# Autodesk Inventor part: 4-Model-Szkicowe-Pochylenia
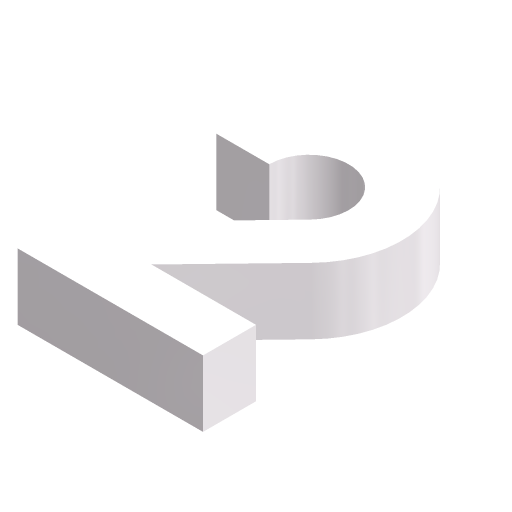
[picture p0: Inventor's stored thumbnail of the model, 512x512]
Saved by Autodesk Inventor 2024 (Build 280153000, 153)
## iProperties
Company: ATC
Shininess: 21.0
Length Units: 11269
Angle Units: 11279
Time Units: 11290
Mass Units: 11283
Length Display Precision: 3
Angle Display Precision: 2
Compacted: True
Created: 2023-03
Part Number: 4-Model-Szkicowe-Pochylenia
Document SubType Name: Modeling
Designer: Andrzej Jaskulski
Material: Kurs-AJ
Density: 1 g/cm^3
Appearance: Kurs-AJ
Checked By: A.J.
Engr Approved By: Andrzej Jaskulski
Mfg Approved By: Andrzej Jaskulski
Authority: A.J.
Density: 0.0
Volumn: 0.0
Area: 0.0
PropertySet Name: Model Information
Control State: 0
Master: False
Checked Out: False
Title: A.J.: Kurs R2024-MEP
Author: Andrzej Jaskulski
Revision Number: 1/24
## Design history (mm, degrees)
sketch "Zarys dwójki"
  geometry: L1 (140, 0.063)-(0, 0.063) reference; L2 (0, 0.063)-(0, 34.389) reference; L3 (0, 150.063)-(40, 150.063); L4 (140, 0.063)-(140, 40.063); L5 (140, 40.063)-(61.086, 40.063); L6 (61.086, 40.063)-(120.354, 101.437); L7 (91.58, 129.223)-(0, 34.389); A1 r 30 centre (70, 150.063) between (91.58, 129.223) and (40, 150.063); A2 r 70 centre (70, 150.063) between (120.354, 101.437) and (0, 150.063)
  constraints: 14 end point, 4 perpendicular, 4 point on circle, 2 centre point, 2 parallel, 2 tangent, 1 coincident
  dimensions: "d0" = 140 distance of L1.start L1.end; "d1" = 150 vertical distance of A1.centre L1.end; "d2" = 70 horizontal distance of L1.end A1.centre; "d3" = 46 deg angle of L6 L5; "d4" = 150 distance of L3.start L1.end (= d1); "d5" = 30 radius of A1; "d6" = 70 radius of A2
extrude "Dwójka" new body sketch "Zarys dwójki" distance "d7" = 50; taper "d8" = 0 deg
node "Płaszczyzna Symetrii"
node "Bryła1"
node "Korpusy bryłowe"
node "Korpusy powierzchniowe"
other parameters: "d9" = 90 deg
